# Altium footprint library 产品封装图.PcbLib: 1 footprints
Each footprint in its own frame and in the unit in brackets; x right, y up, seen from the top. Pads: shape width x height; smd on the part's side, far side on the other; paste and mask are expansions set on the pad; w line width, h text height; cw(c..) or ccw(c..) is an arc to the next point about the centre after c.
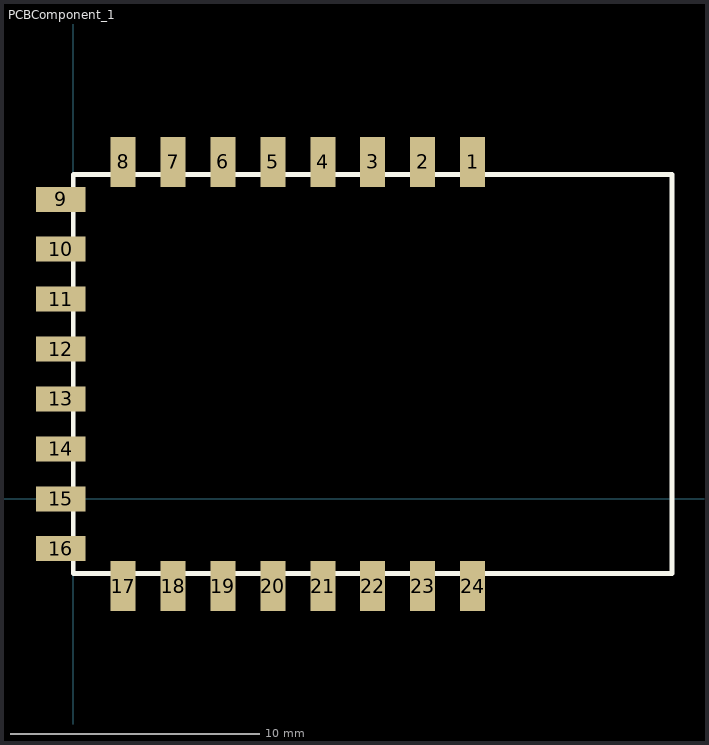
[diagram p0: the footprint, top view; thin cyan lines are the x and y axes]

## PCBComponent_1 [mm]
pads (24):
  rect 1x2 smd: 1(16,13.5) 2(14,13.5) 3(12,13.5) 4(10,13.5) 5(8,13.5) 6(6,13.5) 7(4,13.5) 8(2,13.5) 17(2,-3.5) 18(4,-3.5) 19(6,-3.5) 20(8,-3.5) 21(10,-3.5) 22(12,-3.5) 23(14,-3.5) 24(16,-3.5)
  rect 2x1 smd: 9(-0.5,12) 10(-0.5,10) 11(-0.5,8) 12(-0.5,6) 13(-0.5,4) 14(-0.5,2) 15(-0.5,0) 16(-0.5,-2)
Top Overlay:
  lines w0.2: 0,-3 24,-3 24,13 0,13 0,-3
